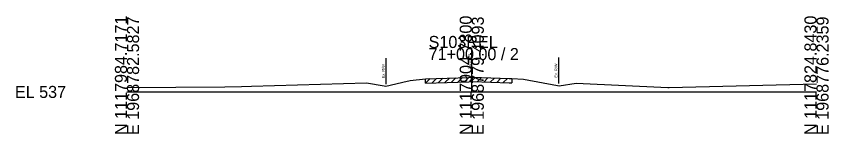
# Model space of a CAD drawing. Extents: x -26 to 163, y -10 to 24518.
# Drawn here: x -25.7 to 162.8, y 19490.3 to 19517.5 of the extents above; entities that cross this region are included whole.
import ezdxf

# ---------------------------------------------------------------- set-up
doc = ezdxf.new("R2010")
doc.units = 0
for name, color, linetype in [('RD_GPK_XS_Cell', 7, 'Continuous'), ('RD_XS_ExGround', 7, 'Continuous'), ('RD_XS_ExPaveRet', 7, 'Continuous'), ('RD_XS_ExRW', 7, 'Continuous'), ('RD_XS_TX_Elev_EX', 7, 'Continuous')]:
    doc.layers.add(name, color=color, linetype=linetype)

msp = doc.modelspace()

# ---------------------------------------------------------------- linework, layer by layer
at = {"layer": 'RD_GPK_XS_Cell'}
for p, q in [((80, 19500), (80, 19510.18)), ((0, 19500), (80, 19500)), ((80, 19500), (160, 19500))]:
    msp.add_line(p, q, dxfattribs=at)
at = {"layer": 'RD_XS_ExGround'}
msp.add_lwpolyline([(0, 19501), (22.71, 19501.22), (26.54, 19501.29), (28.9, 19501.35), (55.55, 19502.09), (59.7, 19501.38), (60.06, 19501.32), (65.04, 19502.5), (65.42, 19502.6), (65.75, 19502.64), (69.29, 19503.06), (79.31, 19503.37), (80.18, 19503.39), (88.69, 19503.1), (89.32, 19503.08), (92.02, 19502.98), (99.92, 19501.49), (100.29, 19501.42), (104.23, 19502.05), (125.47, 19501.05), (125.84, 19501.04), (160, 19501.85)], dxfattribs=at)
at = {"layer": 'RD_XS_ExPaveRet'}
for p, q in [((69.29, 19502.06), (70.32, 19503.1)), ((69.29, 19502.06), (69.29, 19503.06)), ((69.29, 19502.06), (79.31, 19502.37)), ((70.79, 19502.11), (71.82, 19503.14)), ((72.29, 19502.16), (73.32, 19503.19)), ((73.79, 19502.2), (74.82, 19503.23)), ((75.29, 19502.25), (76.32, 19503.28)), ((76.79, 19502.29), (77.82, 19503.32)), ((78.29, 19502.34), (79.32, 19503.37)), ((79.31, 19502.37), (80.18, 19502.39)), ((79.79, 19502.38), (80.78, 19503.37)), ((80.18, 19502.39), (88.69, 19502.1)), ((81.29, 19502.36), (82.26, 19503.32)), ((82.79, 19502.3), (83.76, 19503.27)), ((84.29, 19502.25), (85.26, 19503.22)), ((85.79, 19502.2), (86.76, 19503.17)), ((87.29, 19502.15), (88.26, 19503.12)), ((88.69, 19502.1), (89.32, 19502.08)), ((89.32, 19503.08), (89.32, 19502.08))]:
    msp.add_line(p, q, dxfattribs=at)
at = {"layer": 'RD_XS_ExRW'}
for p, q in [((60.06, 19507.82), (60.06, 19501.82)), ((100.11, 19507.95), (100.11, 19501.95))]:
    msp.add_line(p, q, dxfattribs=at)

# ---------------------------------------------------------------- texts
at = {"layer": 'RD_GPK_XS_Cell'}
for s, p in [('N 1117984.7171', (0, 19490)), ('E 1968782.5827', (2.8, 19490)), ('N 1117904.7800', (80, 19490)), ('E 1968779.4093', (82.8, 19490)), ('N 1117824.8430', (160, 19490)), ('E 1968776.2359', (162.8, 19490))]:
    msp.add_text(s, height=2.8, rotation=90, dxfattribs=at).set_placement(p)
for s, p in [('S103REL', (70, 19510.18)), ('71+00.00 / 2', (70, 19507.38)), ('EL 537', (-26, 19498.6))]:
    msp.add_text(s, height=2.8, dxfattribs=at).set_placement(p)
at = {"layer": 'RD_XS_ExRW'}
for p in [(59.81, 19503.16), (99.86, 19503.3)]:
    msp.add_text('Ex. R/W ', height=0.65, rotation=90, dxfattribs=at).set_placement(p)
at = {"layer": 'RD_XS_TX_Elev_EX'}
msp.add_text('540.39', height=0.8, rotation=90, dxfattribs=at).set_placement((79.9, 19505.39))

doc.saveas('drawing.dxf')
